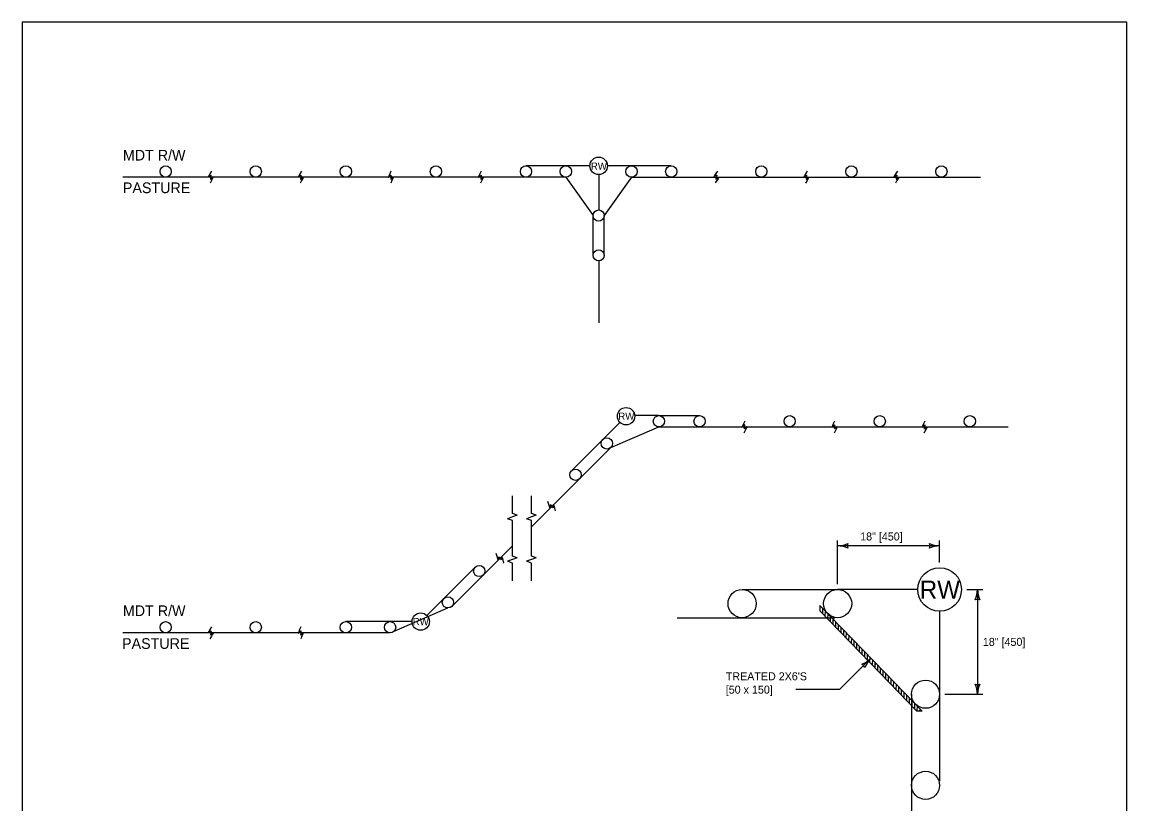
# Model space of a CAD drawing. Extents: x 49991.4 to 50021, y 49987.6 to 50011.4.
# Drawn here: x 50000.34 to 50008.61, y 50005.41 to 50011.26 of the extents above; entities that cross this region are included whole.
import ezdxf

# ---------------------------------------------------------------- set-up
doc = ezdxf.new("R2010")
doc.units = 0
for name, color, linetype in [('Default', 7, 'Continuous'), ('Level 1', 7, 'Continuous'), ('Level 2', 7, 'Continuous'), ('Level 3', 7, 'Continuous'), ('Level 6', 7, 'Continuous')]:
    doc.layers.add(name, color=color, linetype=linetype)

msp = doc.modelspace()

# ---------------------------------------------------------------- linework, layer by layer
at = {"layer": 'Default'}
for p, q in [((50004.6563, 50010.1859), (50004.6563, 50010.1859)), ((50004.1114, 50010.1015), (50004.1114, 50010.1015)), ((50004.9024, 50010.1015), (50007.5169, 50010.1015)), ((50004.6563, 50009.4735), (50004.6563, 50009.4735)), ((50004.8615, 50008.3104), (50004.8615, 50008.3104)), ((50004.8616, 50008.3147), (50004.8616, 50008.3147)), ((50003.3229, 50006.7718), (50003.3229, 50006.7718)), ((50003.3229, 50006.7718), (50003.3229, 50006.7718)), ((50003.3229, 50006.7718), (50003.3229, 50006.7718))]:
    msp.add_line(p, q, dxfattribs=at)
at = {"layer": 'Level 1'}
for p, q in [((50004.4103, 50010.1859), (50004.1114, 50010.1859)), ((50005.1999, 50010.1859), (50004.9024, 50010.1859)), ((50004.4103, 50010.1015), (50001.0908, 50010.1015)), ((50004.4103, 50010.1015), (50004.6142, 50009.8132)), ((50004.9024, 50010.1015), (50004.6985, 50009.8132)), ((50004.6142, 50009.5157), (50004.6142, 50009.8132)), ((50004.6985, 50009.5157), (50004.6985, 50009.8132)), ((50004.6563, 50009.4735), (50004.6563, 50009.0107)), ((50005.1074, 50008.3147), (50005.4129, 50008.3147)), ((50004.7471, 50008.0768), (50005.1074, 50008.2303)), ((50005.1074, 50008.2303), (50007.7248, 50008.2303)), ((50004.7471, 50008.0768), (50004.1546, 50007.4843)), ((50004.6875, 50008.1364), (50004.4526, 50007.9016)), ((50004.0123, 50007.342), (50003.5565, 50006.8862)), ((50003.7317, 50007.1807), (50003.4968, 50006.9458)), ((50005.731, 50007.0122), (50006.447, 50007.0122)), ((50003.1233, 50006.6998), (50003.5267, 50006.8738)), ((50006.3133, 50006.8931), (50006.3127, 50006.8531)), ((50006.3133, 50006.8931), (50006.3127, 50006.8531)), ((50006.3127, 50006.8531), (50006.7656, 50006.3861)), ((50006.8779, 50006.3109), (50006.3133, 50006.8931)), ((50006.8779, 50006.3109), (50006.3133, 50006.8931)), ((50006.333, 50006.8728), (50006.3324, 50006.8328)), ((50006.333, 50006.8728), (50006.3324, 50006.8328)), ((50006.3527, 50006.8525), (50006.3521, 50006.8125)), ((50006.3527, 50006.8525), (50006.3521, 50006.8125)), ((50006.3724, 50006.8322), (50006.3718, 50006.7922)), ((50006.3724, 50006.8322), (50006.3718, 50006.7922)), ((50003.0935, 50006.7718), (50002.7614, 50006.7718)), ((50005.2444, 50006.8013), (50006.4267, 50006.8013)), ((50006.3921, 50006.8119), (50006.3915, 50006.7719)), ((50006.3921, 50006.8119), (50006.3915, 50006.7719)), ((50006.4118, 50006.7916), (50006.4112, 50006.7516)), ((50006.4118, 50006.7916), (50006.4112, 50006.7516)), ((50006.4315, 50006.7713), (50006.4308, 50006.7313)), ((50006.4315, 50006.7713), (50006.4308, 50006.7313)), ((50006.4511, 50006.7509), (50006.4505, 50006.711)), ((50006.4511, 50006.7509), (50006.4505, 50006.711)), ((50003.0935, 50006.6875), (50001.0908, 50006.6875)), ((50006.4708, 50006.7306), (50006.4702, 50006.6906)), ((50006.4708, 50006.7306), (50006.4702, 50006.6906)), ((50006.4905, 50006.7103), (50006.4899, 50006.6703)), ((50006.4905, 50006.7103), (50006.4899, 50006.6703)), ((50006.5102, 50006.69), (50006.5096, 50006.65)), ((50006.5102, 50006.69), (50006.5096, 50006.65)), ((50006.5299, 50006.6697), (50006.5293, 50006.6297)), ((50006.5299, 50006.6697), (50006.5293, 50006.6297)), ((50006.5496, 50006.6494), (50006.549, 50006.6094)), ((50006.5496, 50006.6494), (50006.549, 50006.6094)), ((50006.5693, 50006.6291), (50006.5687, 50006.5891)), ((50006.5693, 50006.6291), (50006.5687, 50006.5891)), ((50006.589, 50006.6088), (50006.5884, 50006.5688)), ((50006.589, 50006.6088), (50006.5884, 50006.5688)), ((50006.6087, 50006.5885), (50006.6081, 50006.5485)), ((50006.6087, 50006.5885), (50006.6081, 50006.5485)), ((50006.6284, 50006.5682), (50006.6278, 50006.5282)), ((50006.6284, 50006.5682), (50006.6278, 50006.5282)), ((50006.6481, 50006.5479), (50006.6474, 50006.5079)), ((50006.6481, 50006.5479), (50006.6474, 50006.5079)), ((50006.6677, 50006.5276), (50006.6671, 50006.4876)), ((50006.6677, 50006.5276), (50006.6671, 50006.4876)), ((50006.6874, 50006.5073), (50006.6868, 50006.4673)), ((50006.6874, 50006.5073), (50006.6868, 50006.4673)), ((50006.7071, 50006.487), (50006.7065, 50006.447)), ((50006.7071, 50006.487), (50006.7065, 50006.447)), ((50006.7073, 50006.4869), (50006.7067, 50006.4469)), ((50006.7073, 50006.4869), (50006.7067, 50006.4469)), ((50006.7268, 50006.4667), (50006.7262, 50006.4267)), ((50006.7268, 50006.4667), (50006.7262, 50006.4267)), ((50006.727, 50006.4666), (50006.7264, 50006.4266)), ((50006.727, 50006.4666), (50006.7264, 50006.4266)), ((50006.7465, 50006.4464), (50006.7459, 50006.4064)), ((50006.7465, 50006.4464), (50006.7459, 50006.4064)), ((50006.7467, 50006.4463), (50006.7461, 50006.4063)), ((50006.7467, 50006.4463), (50006.7461, 50006.4063)), ((50006.7662, 50006.4261), (50006.7656, 50006.3861)), ((50006.7662, 50006.4261), (50006.7656, 50006.3861)), ((50006.7664, 50006.426), (50006.7658, 50006.386)), ((50006.7664, 50006.426), (50006.7658, 50006.386)), ((50006.7859, 50006.4058), (50006.7853, 50006.3658)), ((50006.7859, 50006.4058), (50006.7853, 50006.3658)), ((50006.7861, 50006.4057), (50006.7855, 50006.3657)), ((50006.7861, 50006.4057), (50006.7855, 50006.3657)), ((50006.7656, 50006.3861), (50007.0415, 50006.1017)), ((50006.8056, 50006.3855), (50006.805, 50006.3455)), ((50006.8056, 50006.3855), (50006.805, 50006.3455)), ((50006.8058, 50006.3854), (50006.8052, 50006.3454)), ((50006.8058, 50006.3854), (50006.8052, 50006.3454)), ((50006.8253, 50006.3652), (50006.8247, 50006.3252)), ((50006.8253, 50006.3652), (50006.8247, 50006.3252)), ((50006.8255, 50006.3651), (50006.8249, 50006.3251)), ((50006.8255, 50006.3651), (50006.8249, 50006.3251)), ((50006.845, 50006.3449), (50006.8445, 50006.3114)), ((50006.845, 50006.3449), (50006.8445, 50006.3114)), ((50006.8452, 50006.3448), (50006.8446, 50006.3048)), ((50006.8452, 50006.3448), (50006.8446, 50006.3048)), ((50006.8649, 50006.3245), (50006.8642, 50006.2845)), ((50006.8649, 50006.3245), (50006.8642, 50006.2845)), ((50006.8647, 50006.3246), (50006.8645, 50006.3111)), ((50006.8647, 50006.3246), (50006.8645, 50006.3111)), ((50006.8779, 50006.3109), (50007.0815, 50006.1011)), ((50006.8845, 50006.3042), (50006.8839, 50006.2642)), ((50006.8845, 50006.3042), (50006.8839, 50006.2642)), ((50006.9042, 50006.2839), (50006.9036, 50006.2439)), ((50006.9042, 50006.2839), (50006.9036, 50006.2439)), ((50006.9239, 50006.2636), (50006.9233, 50006.2236)), ((50006.9239, 50006.2636), (50006.9233, 50006.2236)), ((50006.9436, 50006.2433), (50006.943, 50006.2033)), ((50006.9436, 50006.2433), (50006.943, 50006.2033)), ((50006.9633, 50006.223), (50006.9627, 50006.183)), ((50006.9633, 50006.223), (50006.9627, 50006.183)), ((50006.983, 50006.2026), (50006.9824, 50006.1627)), ((50006.983, 50006.2026), (50006.9824, 50006.1627)), ((50007.0001, 50006.2278), (50007.0001, 50005.1218)), ((50007.0027, 50006.1823), (50007.0021, 50006.1423)), ((50007.0027, 50006.1823), (50007.0021, 50006.1423)), ((50007.0224, 50006.162), (50007.0218, 50006.122)), ((50007.0224, 50006.162), (50007.0218, 50006.122)), ((50007.2111, 50006.2278), (50007.2111, 50005.5766)), ((50007.0421, 50006.1417), (50007.0415, 50006.1017)), ((50007.0421, 50006.1417), (50007.0415, 50006.1017)), ((50007.0815, 50006.1011), (50007.0415, 50006.1017)), ((50007.0618, 50006.1214), (50007.0615, 50006.1014))]:
    msp.add_line(p, q, dxfattribs=at)
msp.add_lwpolyline([(50008.6146, 50011.2628), (50000.3356, 50011.2628), (50000.3356, 50000.0624), (50008.6146, 50000.0624)], close=True, dxfattribs=at)
for centre, radius in [((50001.4114, 50010.1437), 0.0422), ((50002.0864, 50010.1437), 0.0422), ((50002.7614, 50010.1437), 0.0422), ((50003.4364, 50010.1437), 0.0422), ((50004.1114, 50010.1437), 0.0422), ((50004.4103, 50010.1437), 0.0422), ((50004.9024, 50010.1437), 0.0422), ((50005.1999, 50010.1437), 0.0422), ((50005.8749, 50010.1437), 0.0422), ((50006.5499, 50010.1437), 0.0422), ((50007.2249, 50010.1437), 0.0422), ((50004.6563, 50009.8132), 0.0422), ((50004.6563, 50009.5157), 0.0422), ((50005.1074, 50008.2725), 0.0422), ((50005.4126, 50008.2725), 0.0422), ((50006.0876, 50008.2725), 0.0422), ((50006.7626, 50008.2725), 0.0422), ((50007.4376, 50008.2725), 0.0422), ((50004.7173, 50008.1066), 0.0422), ((50004.4825, 50007.8718), 0.0422), ((50003.7615, 50007.1508), 0.0422), ((50005.731, 50006.9067), 0.1055), ((50006.447, 50006.9067), 0.1055), ((50003.5267, 50006.916), 0.0422), ((50001.4114, 50006.7296), 0.0422), ((50002.0864, 50006.7296), 0.0422), ((50002.7614, 50006.7296), 0.0422), ((50003.0935, 50006.7296), 0.0422), ((50007.1056, 50006.2278), 0.1055), ((50007.1056, 50005.5453), 0.1055)]:
    msp.add_circle(centre, radius, dxfattribs=at)
for points in [[(50001.7537, 50010.146), (50001.7337, 50010.1033), (50001.7504, 50010.1169), (50001.7474, 50010.0864), (50001.7641, 50010.1), (50001.7442, 50010.0571)], [(50002.4287, 50010.146), (50002.4087, 50010.1033), (50002.4253, 50010.1169), (50002.4224, 50010.0864), (50002.4391, 50010.1), (50002.4192, 50010.0571)], [(50003.1, 50010.1459), (50003.0835, 50010.1017), (50003.0991, 50010.1165), (50003.0986, 50010.086), (50003.1141, 50010.1008), (50003.0978, 50010.0565)], [(50003.7769, 50010.1457), (50003.7586, 50010.1023), (50003.7747, 50010.1165), (50003.7729, 50010.0859), (50003.7891, 50010.1001), (50003.7709, 50010.0565)], [(50005.5469, 50010.1452), (50005.5225, 50010.1048), (50005.5405, 50010.1166), (50005.5344, 50010.0866), (50005.5524, 50010.0983), (50005.5282, 50010.0577)], [(50006.2178, 50010.1457), (50006.1972, 50010.1032), (50006.2141, 50010.1166), (50006.2107, 50010.0862), (50006.2276, 50010.0996), (50006.2072, 50010.0569)], [(50006.8954, 50010.1454), (50006.8724, 50010.1042), (50006.89, 50010.1165), (50006.8849, 50010.0864), (50006.9025, 50010.0987), (50006.8796, 50010.0573)], [(50005.746, 50008.1863), (50005.7652, 50008.2299), (50005.749, 50008.2162), (50005.7513, 50008.2464), (50005.7351, 50008.2326), (50005.7535, 50008.2762)], [(50006.4234, 50008.1853), (50006.4402, 50008.2299), (50006.4248, 50008.2153), (50006.4255, 50008.2456), (50006.4101, 50008.231), (50006.4261, 50008.2755)], [(50007.0954, 50008.1851), (50007.1151, 50008.2285), (50007.0987, 50008.2149), (50007.1014, 50008.2451), (50007.0851, 50008.2315), (50007.1039, 50008.2749)], [(50004.333, 50007.6012), (50004.3162, 50007.6458), (50004.3143, 50007.6247), (50004.2949, 50007.6479), (50004.2929, 50007.6267), (50004.2755, 50007.6708)], [(50003.9447, 50007.2103), (50003.929, 50007.2552), (50003.9265, 50007.2341), (50003.9077, 50007.2579), (50003.9052, 50007.2368), (50003.8889, 50007.2813)], [(50001.755, 50006.7318), (50001.7337, 50006.6897), (50001.7508, 50006.7027), (50001.747, 50006.6724), (50001.764, 50006.6855), (50001.7429, 50006.6431)], [(50002.4243, 50006.7316), (50002.4085, 50006.6871), (50002.4238, 50006.7023), (50002.4238, 50006.6717), (50002.4391, 50006.6868), (50002.4235, 50006.6422)]]:
    msp.add_spline(points, degree=3, dxfattribs=at)
at = {"layer": 'Level 2'}
for centre, radius in [((50004.6563, 50010.1859), 0.0653), ((50004.8615, 50008.3104), 0.0653), ((50007.2111, 50007.0122), 0.1634), ((50003.3229, 50006.7718), 0.0653)]:
    msp.add_circle(centre, radius, dxfattribs=at)
at = {"layer": 'Level 3'}
for p, q in [((50004.591, 50010.1859), (50004.399, 50010.1859)), ((50004.9024, 50010.1859), (50004.7217, 50010.1859)), ((50004.6563, 50010.1205), (50004.6563, 50009.8554)), ((50005.1074, 50008.3147), (50004.9267, 50008.3147)), ((50004.8153, 50008.2642), (50004.6875, 50008.1364)), ((50006.447, 50007.0522), (50006.447, 50007.3796)), ((50007.2111, 50007.3396), (50006.447, 50007.3396)), ((50007.2111, 50007.2156), (50007.2111, 50007.3796)), ((50007.0477, 50007.0122), (50006.447, 50007.0122)), ((50007.4144, 50007.0122), (50007.5351, 50007.0122)), ((50007.4951, 50007.0122), (50007.4951, 50006.2278)), ((50003.4968, 50006.9458), (50003.3691, 50006.818)), ((50007.2111, 50006.8489), (50007.2111, 50006.2278)), ((50003.2575, 50006.7718), (50003.0935, 50006.7718)), ((50007.2511, 50006.2278), (50007.5351, 50006.2278))]:
    msp.add_line(p, q, dxfattribs=at)
msp.add_lwpolyline([(50006.6934, 50006.4945), (50006.461, 50006.2622), (50006.461, 50006.2622), (50006.1337, 50006.2622)], dxfattribs=at)
for centre, radius, start, end in [((50006.4355, 50007.5723), 0.233, 272.82731, 292.07716), ((50006.4378, 50007.1174), 0.2223, 67.45601, 87.63952), ((50006.5752, 50007.3396), 0.0548, 162.13882, 197.86118), ((50007.2202, 50007.5617), 0.2223, 247.45601, 267.63952), ((50007.0828, 50007.3396), 0.0548, 342.13882, 17.86118), ((50007.2226, 50007.1069), 0.233, 92.82731, 112.07716), ((50007.273, 50007.0214), 0.2223, 337.45601, 357.63952), ((50007.7278, 50007.0237), 0.233, 182.82731, 202.07716), ((50007.4951, 50006.884), 0.0548, 72.13882, 107.86118), ((50006.5428, 50006.6581), 0.2223, 292.45601, 312.63952), ((50006.8661, 50006.3381), 0.233, 137.82731, 157.07716), ((50006.6027, 50006.4039), 0.0548, 27.13882, 62.86118), ((50007.4951, 50006.356), 0.0548, 252.13882, 287.86118), ((50007.2624, 50006.2163), 0.233, 2.82731, 22.07716), ((50007.7172, 50006.2187), 0.2223, 157.45601, 177.63952)]:
    msp.add_arc(centre, radius, start, end, dxfattribs=at)
at = {"layer": 'Level 6'}
for p, q in [((50004.0101, 50007.5814), (50004.0101, 50007.7149)), ((50004.1524, 50007.5814), (50004.1524, 50007.7149)), ((50004.0467, 50007.5685), (50004.0101, 50007.5814)), ((50004.0467, 50007.5685), (50004.0101, 50007.5555)), ((50004.189, 50007.5685), (50004.1524, 50007.5814)), ((50004.189, 50007.5685), (50004.1524, 50007.5555)), ((50004.0101, 50007.5555), (50003.9735, 50007.5425)), ((50004.0101, 50007.5296), (50003.9735, 50007.5425)), ((50004.0101, 50007.2625), (50004.0101, 50007.5296)), ((50004.1524, 50007.5555), (50004.1158, 50007.5425)), ((50004.1524, 50007.5296), (50004.1158, 50007.5425)), ((50004.1524, 50007.2625), (50004.1524, 50007.5296)), ((50004.0101, 50007.2366), (50003.9735, 50007.2236)), ((50004.0467, 50007.2496), (50004.0101, 50007.2625)), ((50004.0467, 50007.2496), (50004.0101, 50007.2366)), ((50004.1524, 50007.2366), (50004.1158, 50007.2236)), ((50004.189, 50007.2496), (50004.1524, 50007.2625)), ((50004.189, 50007.2496), (50004.1524, 50007.2366)), ((50004.0101, 50007.2107), (50003.9735, 50007.2236)), ((50004.0101, 50007.0772), (50004.0101, 50007.2107)), ((50004.1524, 50007.2107), (50004.1158, 50007.2236)), ((50004.1524, 50007.0772), (50004.1524, 50007.2107))]:
    msp.add_line(p, q, dxfattribs=at)

# ---------------------------------------------------------------- texts
at = {"layer": 'Level 2'}
for s, height, p in [('MDT R/W', 0.08, (50001.0908, 50010.2259)), ('RW', 0.054, (50004.5975, 50010.1567)), ('PASTURE', 0.08, (50001.0908, 50009.9815)), ('RW', 0.054, (50004.8032, 50008.2834)), ('18" [450]', 0.06, (50006.6158, 50007.3796)), ('RW', 0.13509, (50007.0626, 50006.9443)), ('MDT R/W', 0.08, (50001.0908, 50006.8133)), ('RW', 0.054, (50003.263, 50006.7447)), ('18" [450]', 0.06, (50007.5351, 50006.59)), ('PASTURE', 0.08, (50001.0847, 50006.5675)), ("TREATED 2X6'S ", 0.06, (50005.6087, 50006.3322)), ('[50 x 150]', 0.06, (50005.6087, 50006.2322))]:
    msp.add_text(s, height=height, dxfattribs=at).set_placement(p)

doc.saveas('drawing.dxf')
